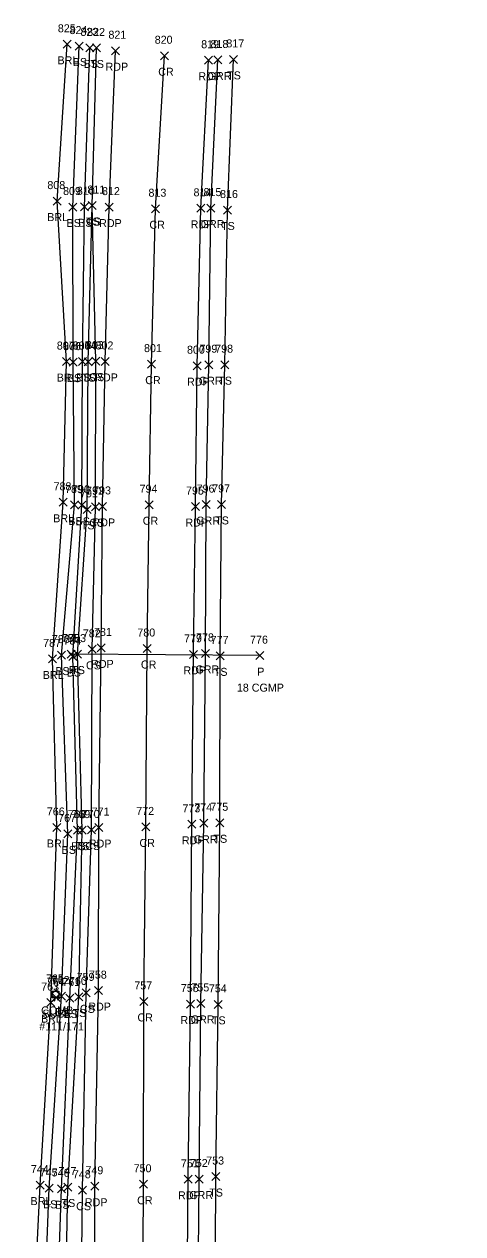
# Model space of a CAD drawing. Extents: x 1879695 to 1880991, y 836466 to 845172.
# Drawn here: x 1879783.3 to 1879892.9, y 844869.6 to 845171.9 of the extents above; entities that cross this region are included whole.
import ezdxf

# ---------------------------------------------------------------- set-up
doc = ezdxf.new("R2010")
doc.units = 0
for name, color, linetype in [('D_A', 7, 'Continuous'), ('D_C', 7, 'Continuous'), ('D_I', 7, 'Continuous'), ('D_TIC', 7, 'Continuous'), ('DCP', 7, 'Continuous'), ('L_A', 7, 'Continuous'), ('L_I', 7, 'Continuous'), ('L_TIC', 7, 'Continuous'), ('LABL', 7, 'Continuous'), ('LELB', 7, 'Continuous'), ('P_A', 7, 'Continuous'), ('P_I', 7, 'Continuous'), ('P_TIC', 7, 'Continuous'), ('PET', 7, 'Continuous'), ('PRC', 7, 'Continuous'), ('R_A', 7, 'Continuous'), ('R_I', 7, 'Continuous'), ('R_TIC', 7, 'Continuous'), ('RGR', 7, 'Continuous'), ('U_A', 7, 'Continuous'), ('U_C', 7, 'Continuous'), ('U_I', 7, 'Continuous'), ('U_TIC', 7, 'Continuous'), ('UP', 7, 'Continuous')]:
    doc.layers.add(name, color=color, linetype=linetype)

msp = doc.modelspace()

# ---------------------------------------------------------------- linework, layer by layer
at = {"layer": 'D_TIC'}
for points in [[(1879794.03, 845013.48), (1879796.03, 845015.48)], [(1879796.03, 845013.48), (1879794.03, 845015.48)], [(1879841.13, 845013.09), (1879843.13, 845015.09)], [(1879843.13, 845013.09), (1879841.13, 845015.09)]]:
    msp.add_lwpolyline(points, dxfattribs=at)
at = {"layer": 'DCP'}
msp.add_lwpolyline([(1879842.13, 845014.09), (1879795.03, 845014.48)], dxfattribs=at)
at = {"layer": 'L_TIC'}
for points in [[(1879793.05, 845165.9), (1879795.05, 845167.9)], [(1879795.05, 845165.9), (1879793.05, 845167.9)], [(1879795.98, 845165.46), (1879797.98, 845167.46)], [(1879797.98, 845165.46), (1879795.98, 845167.46)], [(1879798.71, 845165.01), (1879800.71, 845167.01)], [(1879800.71, 845165.01), (1879798.71, 845167.01)], [(1879800.38, 845164.98), (1879802.38, 845166.98)], [(1879802.38, 845164.98), (1879800.38, 845166.98)], [(1879834.58, 845162.13), (1879836.58, 845164.13)], [(1879836.58, 845162.13), (1879834.58, 845164.13)], [(1879790.51, 845126.71), (1879792.51, 845128.71)], [(1879792.51, 845126.71), (1879790.51, 845128.71)], [(1879794.44, 845125.23), (1879796.44, 845127.23)], [(1879796.44, 845125.23), (1879794.44, 845127.23)], [(1879797.32, 845125.29), (1879799.32, 845127.29)], [(1879799.32, 845125.29), (1879797.32, 845127.29)], [(1879799.29, 845125.59), (1879801.29, 845127.59)], [(1879801.29, 845125.59), (1879799.29, 845127.59)], [(1879799.29, 845125.59), (1879801.29, 845127.59)], [(1879801.29, 845125.59), (1879799.29, 845127.59)], [(1879833.06, 845124.48), (1879835.06, 845126.48)], [(1879835.06, 845124.48), (1879833.06, 845126.48)], [(1879792.87, 845086.6), (1879794.87, 845088.6)], [(1879794.87, 845086.6), (1879792.87, 845088.6)], [(1879794.49, 845086.45), (1879796.49, 845088.45)], [(1879796.49, 845086.45), (1879794.49, 845088.45)], [(1879796.82, 845086.62), (1879798.82, 845088.62)], [(1879798.82, 845086.62), (1879796.82, 845088.62)], [(1879798.3, 845086.57), (1879800.3, 845088.57)], [(1879800.3, 845086.57), (1879798.3, 845088.57)], [(1879800.14, 845086.72), (1879802.14, 845088.72)], [(1879802.14, 845086.72), (1879800.14, 845088.72)], [(1879832.37, 845085.82), (1879834.37, 845087.82)], [(1879834.37, 845085.82), (1879832.37, 845087.82)], [(1879791.98, 845051.42), (1879793.98, 845053.42)], [(1879793.98, 845051.42), (1879791.98, 845053.42)], [(1879794.86, 845050.75), (1879796.86, 845052.75)], [(1879796.86, 845050.75), (1879794.86, 845052.75)], [(1879796.69, 845050.68), (1879798.69, 845052.68)], [(1879798.69, 845050.68), (1879796.69, 845052.68)], [(1879831.59, 845050.89), (1879833.59, 845052.89)], [(1879833.59, 845050.89), (1879831.59, 845052.89)], [(1879798.04, 845049.66), (1879800.04, 845051.66)], [(1879800.04, 845049.66), (1879798.04, 845051.66)], [(1879800.11, 845050.3), (1879802.11, 845052.3)], [(1879802.11, 845050.3), (1879800.11, 845052.3)], [(1879799.28, 845014.67), (1879801.28, 845016.67)], [(1879801.28, 845014.67), (1879799.28, 845016.67)], [(1879789.38, 845012.26), (1879791.38, 845014.26)], [(1879791.38, 845012.26), (1879789.38, 845014.26)], [(1879791.62, 845013.23), (1879793.62, 845015.23)], [(1879793.62, 845013.23), (1879791.62, 845015.23)], [(1879794.45, 845012.86), (1879796.45, 845014.86)], [(1879796.45, 845012.86), (1879794.45, 845014.86)], [(1879795.62, 845013.48), (1879797.62, 845015.48)], [(1879797.62, 845013.48), (1879795.62, 845015.48)], [(1879831.24, 845013.04), (1879833.24, 845015.04)], [(1879833.24, 845013.04), (1879831.24, 845015.04)], [(1879790.41, 844970.14), (1879792.41, 844972.14)], [(1879792.41, 844970.14), (1879790.41, 844972.14)], [(1879795.6, 844969.46), (1879797.6, 844971.46)], [(1879797.6, 844969.46), (1879795.6, 844971.46)], [(1879796.73, 844969.48), (1879798.73, 844971.48)], [(1879798.73, 844969.48), (1879796.73, 844971.48)], [(1879799.12, 844969.52), (1879801.12, 844971.52)], [(1879801.12, 844969.52), (1879799.12, 844971.52)], [(1879831.17, 844971.31), (1879833.17, 844973.31)], [(1879833.17, 844971.31), (1879831.17, 844973.31)], [(1879793.18, 844968.53), (1879795.18, 844970.53)], [(1879795.18, 844968.53), (1879793.18, 844970.53)], [(1879791.57, 844928), (1879793.57, 844930)], [(1879793.57, 844928), (1879791.57, 844930)], [(1879793.66, 844927.51), (1879795.66, 844929.51)], [(1879795.66, 844927.51), (1879793.66, 844929.51)], [(1879795.97, 844927.77), (1879797.97, 844929.77)], [(1879797.97, 844927.77), (1879795.97, 844929.77)], [(1879797.76, 844928.8), (1879799.76, 844930.8)], [(1879799.76, 844928.8), (1879797.76, 844930.8)], [(1879788.94, 844926.36), (1879790.94, 844928.36)], [(1879790.94, 844926.36), (1879788.94, 844928.36)], [(1879830.78, 844925.93), (1879832.78, 844927.93)], [(1879832.78, 844925.93), (1879830.78, 844927.93)], [(1879830.12, 844882.89), (1879832.12, 844884.89)], [(1879832.12, 844882.89), (1879830.12, 844884.89)], [(1879786.31, 844880.75), (1879788.31, 844882.75)], [(1879788.31, 844880.75), (1879786.31, 844882.75)], [(1879788.53, 844879.94), (1879790.53, 844881.94)], [(1879790.53, 844879.94), (1879788.53, 844881.94)], [(1879791.57, 844879.83), (1879793.57, 844881.83)], [(1879793.57, 844879.83), (1879791.57, 844881.83)], [(1879793.22, 844880.27), (1879795.22, 844882.27)], [(1879795.22, 844880.27), (1879793.22, 844882.27)], [(1879796.81, 844879.47), (1879798.81, 844881.47)], [(1879798.81, 844879.47), (1879796.81, 844881.47)]]:
    msp.add_lwpolyline(points, dxfattribs=at)
at = {"layer": 'LABL'}
msp.add_lwpolyline([(1879783.28, 844693.1), (1879786.09, 844732.95), (1879784.2, 844776.27), (1879784.93, 844834.09), (1879787.31, 844881.75), (1879789.94, 844927.36), (1879791.41, 844971.14), (1879790.38, 845013.26), (1879792.98, 845052.42), (1879793.87, 845087.6), (1879791.51, 845127.71), (1879794.05, 845166.9)], dxfattribs=at)
at = {"layer": 'LELB'}
for points in [[(1879788.56, 844689.11), (1879788.25, 844733.11), (1879786.93, 844775.7), (1879787.69, 844833.58), (1879789.53, 844880.94), (1879792.57, 844929), (1879794.18, 844969.53), (1879792.62, 845014.23), (1879795.86, 845051.75), (1879795.49, 845087.45), (1879795.44, 845126.23), (1879796.98, 845166.46)], [(1879840.74, 844478.66), (1879829.75, 844515.78), (1879817.77, 844560.78), (1879808.57, 844599.66), (1879797.58, 844646.67), (1879792.29, 844679.84), (1879789.08, 844683.63), (1879788.58, 844684.77), (1879788.56, 844689.11), (1879790.67, 844689.03), (1879791.23, 844733), (1879790.4, 844776.52), (1879790.9, 844833.29), (1879792.57, 844880.83), (1879794.66, 844928.51), (1879796.6, 844970.46), (1879795.45, 845013.86), (1879797.69, 845051.68), (1879797.82, 845087.62), (1879798.32, 845126.29), (1879799.71, 845166.01)], [(1879826.86, 844562.48), (1879815.22, 844600.52), (1879803.7, 844647.13), (1879796.55, 844686.76), (1879795.21, 844733.25), (1879793.83, 844777.19), (1879793.24, 844833.08), (1879794.22, 844881.27), (1879796.97, 844928.77), (1879797.73, 844970.48), (1879796.62, 845014.48), (1879799.04, 845050.66), (1879799.3, 845087.57), (1879800.29, 845126.59), (1879801.38, 845165.98)], [(1879892.86, 844475.33), (1879883.81, 844493.88), (1879869.59, 844531.53), (1879857.27, 844570.41), (1879848, 844610.42), (1879840.98, 844651.69), (1879836.74, 844689.33), (1879832.5, 844735.02), (1879831.42, 844779.25), (1879830.94, 844828.14), (1879831.12, 844883.89), (1879831.78, 844926.93), (1879832.17, 844972.31), (1879832.24, 845014.04), (1879832.59, 845051.89), (1879833.37, 845086.82), (1879834.06, 845125.48), (1879835.58, 845163.13)], [(1879817.39, 844602.91), (1879808.34, 844648.05), (1879803.4, 844686.5), (1879799.83, 844734.05), (1879798.52, 844777.54), (1879797.37, 844833.31), (1879797.81, 844880.47), (1879798.76, 844929.8), (1879800.12, 844970.52), (1879800.28, 845015.67), (1879801.11, 845051.3), (1879801.14, 845087.72), (1879800.29, 845126.59)]]:
    msp.add_lwpolyline(points, dxfattribs=at)
at = {"layer": 'P_TIC'}
for points in [[(1879805.13, 845164.3), (1879807.13, 845166.3)], [(1879807.13, 845164.3), (1879805.13, 845166.3)], [(1879817.34, 845163.04), (1879819.34, 845165.04)], [(1879819.34, 845163.04), (1879817.34, 845165.04)], [(1879828.31, 845161.92), (1879830.31, 845163.92)], [(1879830.31, 845161.92), (1879828.31, 845163.92)], [(1879803.52, 845125.21), (1879805.52, 845127.21)], [(1879805.52, 845125.21), (1879803.52, 845127.21)], [(1879815.12, 845124.8), (1879817.12, 845126.8)], [(1879817.12, 845124.8), (1879815.12, 845126.8)], [(1879826.38, 845124.9), (1879828.38, 845126.9)], [(1879828.38, 845124.9), (1879826.38, 845126.9)], [(1879802.55, 845086.63), (1879804.55, 845088.63)], [(1879804.55, 845086.63), (1879802.55, 845088.63)], [(1879814.09, 845085.96), (1879816.09, 845087.96)], [(1879816.09, 845085.96), (1879814.09, 845087.96)], [(1879825.48, 845085.56), (1879827.48, 845087.56)], [(1879827.48, 845085.56), (1879825.48, 845087.56)], [(1879813.47, 845050.81), (1879815.47, 845052.81)], [(1879815.47, 845050.81), (1879813.47, 845052.81)], [(1879801.87, 845050.39), (1879803.87, 845052.39)], [(1879803.87, 845050.39), (1879801.87, 845052.39)], [(1879825.07, 845050.35), (1879827.07, 845052.35)], [(1879827.07, 845050.35), (1879825.07, 845052.35)], [(1879801.52, 845015.02), (1879803.52, 845017.02)], [(1879803.52, 845015.02), (1879801.52, 845017.02)], [(1879813, 845014.87), (1879815, 845016.87)], [(1879815, 845014.87), (1879813, 845016.87)], [(1879824.59, 845013.41), (1879826.59, 845015.41)], [(1879826.59, 845013.41), (1879824.59, 845015.41)], [(1879800.95, 844970.12), (1879802.95, 844972.12)], [(1879802.95, 844970.12), (1879800.95, 844972.12)], [(1879812.64, 844970.27), (1879814.64, 844972.27)], [(1879814.64, 844970.27), (1879812.64, 844972.27)], [(1879824.18, 844970.93), (1879826.18, 844972.93)], [(1879826.18, 844970.93), (1879824.18, 844972.93)], [(1879800.81, 844929.36), (1879802.81, 844931.36)], [(1879802.81, 844929.36), (1879800.81, 844931.36)], [(1879812.15, 844926.66), (1879814.15, 844928.66)], [(1879814.15, 844926.66), (1879812.15, 844928.66)], [(1879823.83, 844926), (1879825.83, 844928)], [(1879825.83, 844926), (1879823.83, 844928)], [(1879823.22, 844882.19), (1879825.22, 844884.19)], [(1879825.22, 844882.19), (1879823.22, 844884.19)], [(1879799.95, 844880.46), (1879801.95, 844882.46)], [(1879801.95, 844880.46), (1879799.95, 844882.46)], [(1879812.07, 844880.95), (1879814.07, 844882.95)], [(1879814.07, 844880.95), (1879812.07, 844882.95)]]:
    msp.add_lwpolyline(points, dxfattribs=at)
at = {"layer": 'PET'}
for points in [[(1879829.6, 844563.28), (1879820.43, 844602.23), (1879812.27, 844647.91), (1879806.99, 844687.11), (1879803.24, 844734.23), (1879801.26, 844777.93), (1879800.91, 844833.26), (1879800.95, 844881.46), (1879801.81, 844930.36), (1879801.95, 844971.12), (1879802.52, 845016.02), (1879802.87, 845051.39), (1879803.55, 845087.63), (1879804.52, 845126.21), (1879806.13, 845165.3)], [(1879852.88, 844569.32), (1879843.17, 844608.03), (1879835.2, 844650.98), (1879830.24, 844688.3), (1879826.01, 844734.72), (1879824.44, 844779.44), (1879823.84, 844833.63), (1879824.22, 844883.19), (1879824.83, 844927), (1879825.18, 844971.93), (1879825.59, 845014.41), (1879826.07, 845051.35), (1879826.48, 845086.56), (1879827.38, 845125.9), (1879829.31, 845162.92)]]:
    msp.add_lwpolyline(points, dxfattribs=at)
at = {"layer": 'PRC'}
msp.add_lwpolyline([(1879841.81, 844566.38), (1879832.13, 844605), (1879823.88, 844649.84), (1879818.74, 844688.1), (1879815.01, 844734.04), (1879813.56, 844778.55), (1879812.88, 844832.71), (1879813.07, 844881.95), (1879813.15, 844927.66), (1879813.64, 844971.27), (1879814, 845015.87), (1879814.47, 845051.81), (1879815.09, 845086.96), (1879816.12, 845125.8), (1879818.34, 845164.04)], dxfattribs=at)
at = {"layer": 'R_TIC'}
for points in [[(1879830.63, 845161.98), (1879832.63, 845163.98)], [(1879832.63, 845161.98), (1879830.63, 845163.98)], [(1879828.88, 845124.96), (1879830.88, 845126.96)], [(1879830.88, 845124.96), (1879828.88, 845126.96)], [(1879828.43, 845085.81), (1879830.43, 845087.81)], [(1879830.43, 845085.81), (1879828.43, 845087.81)], [(1879827.78, 845050.84), (1879829.78, 845052.84)], [(1879829.78, 845050.84), (1879827.78, 845052.84)], [(1879827.58, 845013.65), (1879829.58, 845015.65)], [(1879829.58, 845013.65), (1879827.58, 845015.65)], [(1879827.14, 844971.18), (1879829.14, 844973.18)], [(1879829.14, 844971.18), (1879827.14, 844973.18)], [(1879826.42, 844926.16), (1879828.42, 844928.16)], [(1879828.42, 844926.16), (1879826.42, 844928.16)], [(1879826.03, 844882.27), (1879828.03, 844884.27)], [(1879828.03, 844882.27), (1879826.03, 844884.27)]]:
    msp.add_lwpolyline(points, dxfattribs=at)
at = {"layer": 'RGR'}
msp.add_lwpolyline([(1879855.21, 844570.01), (1879845.36, 844608.98), (1879837.63, 844651.18), (1879832.76, 844688.35), (1879828.26, 844734.62), (1879826.87, 844779.28), (1879826.48, 844827.6), (1879827.03, 844883.27), (1879827.42, 844927.16), (1879828.14, 844972.18), (1879828.58, 845014.65), (1879828.78, 845051.84), (1879829.43, 845086.81), (1879829.88, 845125.96), (1879831.63, 845162.98)], dxfattribs=at)
at = {"layer": 'U_TIC'}
for points in [[(1879790.31, 844927.6), (1879792.31, 844929.6)], [(1879792.31, 844927.6), (1879790.31, 844929.6)]]:
    msp.add_lwpolyline(points, dxfattribs=at)
at = {"layer": 'UP'}
for p, q in [((1879790.29, 844928.56), (1879790.29, 844930.23)), ((1879790.29, 844930.23), (1879791.96, 844930.23)), ((1879791.38, 844931.06), (1879791.13, 844930.23)), ((1879791.13, 844929.4), (1879791.13, 844929.4)), ((1879791.96, 844930.23), (1879791.96, 844928.56)), ((1879791.96, 844928.56), (1879790.29, 844928.56)), ((1879790.88, 844927.73), (1879791.13, 844928.56))]:
    msp.add_line(p, q, dxfattribs=at)
msp.add_circle((1879791.13, 844929.4), 0.833, dxfattribs=at)

# ---------------------------------------------------------------- texts
at = {"layer": 'D_A'}
for p in [(1879794.41, 845009.48), (1879841.51, 845009.09)]:
    msp.add_text('P', height=2, dxfattribs=at).set_placement(p)
at = {"layer": 'D_C'}
msp.add_text('18 CGMP', height=2, dxfattribs=at).set_placement((1879836.42, 845005.09))
at = {"layer": 'D_I'}
for s, p in [('785', (1879792.67, 845017.48)), ('776', (1879839.71, 845017.09))]:
    msp.add_text(s, height=2, dxfattribs=at).set_placement(p)
at = {"layer": 'L_A'}
for s, p in [('BRL', (1879791.6, 845161.9)), ('BS', (1879795.42, 845161.46)), ('BS', (1879798.15, 845161.01)), ('TS', (1879799.79, 845160.98)), ('TS', (1879833.99, 845158.13)), ('BRL', (1879789.05, 845122.71)), ('BS', (1879793.88, 845121.23)), ('BS', (1879796.76, 845121.29)), ('TS', (1879798.7, 845121.59)), ('CS', (1879798.74, 845121.59)), ('TS', (1879832.47, 845120.48)), ('BRL', (1879791.41, 845082.6)), ('BS', (1879793.93, 845082.45)), ('BS', (1879796.26, 845082.62)), ('TS', (1879797.71, 845082.57)), ('CS', (1879799.58, 845082.72)), ('TS', (1879831.77, 845081.82)), ('BRL', (1879790.53, 845047.42)), ('BS', (1879794.3, 845046.75)), ('BS', (1879796.13, 845046.68)), ('TS', (1879797.45, 845045.66)), ('CS', (1879799.55, 845046.3)), ('TS', (1879831, 845046.89)), ('BRL', (1879787.92, 845008.26)), ('BS', (1879791.06, 845009.23)), ('BS', (1879793.89, 845008.86)), ('TS', (1879795.03, 845009.48)), ('CS', (1879798.72, 845010.67)), ('TS', (1879830.65, 845009.04)), ('BRL', (1879788.95, 844966.14)), ('TS', (1879830.58, 844967.31)), ('BS', (1879792.62, 844964.53)), ('BS', (1879795.04, 844965.46)), ('TS', (1879796.14, 844965.48)), ('CS', (1879798.56, 844965.52)), ('BS', (1879791.01, 844924)), ('TS', (1879795.38, 844923.77)), ('CS', (1879797.2, 844924.8)), ('BRL', (1879787.48, 844922.36)), ('BS', (1879793.1, 844923.51)), ('TS', (1879830.19, 844921.93)), ('TS', (1879829.52, 844878.89)), ('BRL', (1879784.86, 844876.75)), ('BS', (1879787.98, 844875.94)), ('BS', (1879791.02, 844875.83)), ('TS', (1879792.63, 844876.27)), ('CS', (1879796.26, 844875.47))]:
    msp.add_text(s, height=2, dxfattribs=at).set_placement(p)
at = {"layer": 'L_I'}
for s, p in [('825', (1879791.69, 845169.9)), ('824', (1879794.62, 845169.46)), ('823', (1879797.34, 845169.01)), ('822', (1879799.01, 845168.98)), ('817', (1879833.79, 845166.13)), ('808', (1879789.07, 845130.71)), ('809', (1879792.99, 845129.23)), ('810', (1879796.44, 845129.29)), ('811', (1879799.07, 845129.59)), ('811', (1879799.07, 845129.59)), ('816', (1879832.21, 845128.48)), ('807', (1879791.43, 845090.6)), ('806', (1879792.99, 845090.45)), ('805', (1879795.38, 845090.62)), ('804', (1879796.86, 845090.57)), ('803', (1879798.7, 845090.72)), ('798', (1879831, 845089.82)), ('788', (1879790.62, 845055.42)), ('789', (1879793.49, 845054.75)), ('790', (1879795.24, 845054.68)), ('791', (1879797.25, 845053.66)), ('792', (1879798.74, 845054.3)), ('797', (1879830.23, 845054.89)), ('783', (1879794.26, 845017.48)), ('782', (1879797.92, 845018.67)), ('787', (1879788.01, 845016.26)), ('786', (1879790.2, 845017.23)), ('784', (1879793.09, 845016.86)), ('777', (1879829.88, 845017.04)), ('775', (1879829.8, 844975.31)), ('766', (1879788.94, 844974.14)), ('767', (1879791.77, 844972.53)), ('768', (1879794.19, 844973.46)), ('769', (1879795.31, 844973.48)), ('770', (1879797.67, 844973.52)), ('759', (1879796.39, 844932.8)), ('763', (1879787.53, 844930.36)), ('762', (1879790.16, 844932)), ('761', (1879792.81, 844931.51)), ('760', (1879794.48, 844931.77)), ('754', (1879829.42, 844929.93)), ('744', (1879784.95, 844884.75)), ('747', (1879791.86, 844884.27)), ('753', (1879828.75, 844886.89)), ('745', (1879787.17, 844883.94)), ('746', (1879790.16, 844883.83)), ('748', (1879795.45, 844883.47))]:
    msp.add_text(s, height=2, dxfattribs=at).set_placement(p)
at = {"layer": 'P_A'}
for s, p in [('RDP', (1879803.61, 845160.3)), ('CR', (1879816.77, 845159.04)), ('RDP', (1879826.79, 845157.92)), ('RDP', (1879802.01, 845121.21)), ('CR', (1879814.56, 845120.8)), ('RDP', (1879824.87, 845120.9)), ('RDP', (1879801.03, 845082.63)), ('CR', (1879813.52, 845081.96)), ('RDP', (1879823.97, 845081.56)), ('RDP', (1879800.35, 845046.39)), ('CR', (1879812.9, 845046.81)), ('RDP', (1879823.56, 845046.35)), ('RDP', (1879800.01, 845011.02)), ('CR', (1879812.44, 845010.87)), ('RDP', (1879823.07, 845009.41)), ('RDP', (1879799.44, 844966.12)), ('CR', (1879812.08, 844966.27)), ('RDP', (1879822.67, 844966.93)), ('RDP', (1879799.3, 844925.36)), ('CR', (1879811.58, 844922.66)), ('RDP', (1879822.32, 844922)), ('RDP', (1879798.44, 844876.46)), ('CR', (1879811.5, 844876.95)), ('RDP', (1879821.71, 844878.19))]:
    msp.add_text(s, height=2, dxfattribs=at).set_placement(p)
at = {"layer": 'P_I'}
for s, p in [('821', (1879804.33, 845168.3)), ('820', (1879815.89, 845167.04)), ('819', (1879827.5, 845165.92)), ('812', (1879802.72, 845129.21)), ('813', (1879814.33, 845128.8)), ('814', (1879825.59, 845128.9)), ('802', (1879801.1, 845090.63)), ('801', (1879813.22, 845089.96)), ('800', (1879823.96, 845089.56)), ('793', (1879800.5, 845054.39)), ('794', (1879812.11, 845054.81)), ('795', (1879823.71, 845054.35)), ('781', (1879800.72, 845019.02)), ('780', (1879811.55, 845018.87)), ('779', (1879823.22, 845017.41)), ('773', (1879822.82, 844974.93)), ('771', (1879800.15, 844974.12)), ('772', (1879811.28, 844974.27)), ('758', (1879799.45, 844933.36)), ('757', (1879810.79, 844930.66)), ('756', (1879822.41, 844930)), ('749', (1879798.58, 844884.46)), ('750', (1879810.62, 844884.95)), ('751', (1879822.42, 844886.19))]:
    msp.add_text(s, height=2, dxfattribs=at).set_placement(p)
at = {"layer": 'R_A'}
for p in [(1879829.12, 845157.98), (1879827.37, 845120.96), (1879826.92, 845081.81), (1879826.27, 845046.84), (1879826.07, 845009.65), (1879825.63, 844967.18), (1879824.91, 844922.16), (1879824.52, 844878.27)]:
    msp.add_text('GRR', height=2, dxfattribs=at).set_placement(p)
at = {"layer": 'R_I'}
for s, p in [('818', (1879829.83, 845165.98)), ('815', (1879828.08, 845128.96)), ('799', (1879827.06, 845089.81)), ('796', (1879826.36, 845054.84)), ('778', (1879826.21, 845017.65)), ('774', (1879825.78, 844975.18)), ('755', (1879825.06, 844930.16)), ('752', (1879824.67, 844886.27))]:
    msp.add_text(s, height=2, dxfattribs=at).set_placement(p)
at = {"layer": 'U_A'}
for s, p in [('COMB', (1879787.51, 844924.4)), ('SUBE', (1879787.84, 844923.6))]:
    msp.add_text(s, height=2, dxfattribs=at).set_placement(p)
at = {"layer": 'U_C'}
msp.add_text('#111/171', height=2, dxfattribs=at).set_placement((1879787.03, 844920.4))
at = {"layer": 'U_I'}
for s, p in [('765', (1879788.72, 844932.4)), ('764', (1879788.9, 844931.6))]:
    msp.add_text(s, height=2, dxfattribs=at).set_placement(p)

doc.saveas('drawing.dxf')
